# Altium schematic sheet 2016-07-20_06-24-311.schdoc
size 201 x 114 mm; SheetNumber: 1; SheetTotal: 1
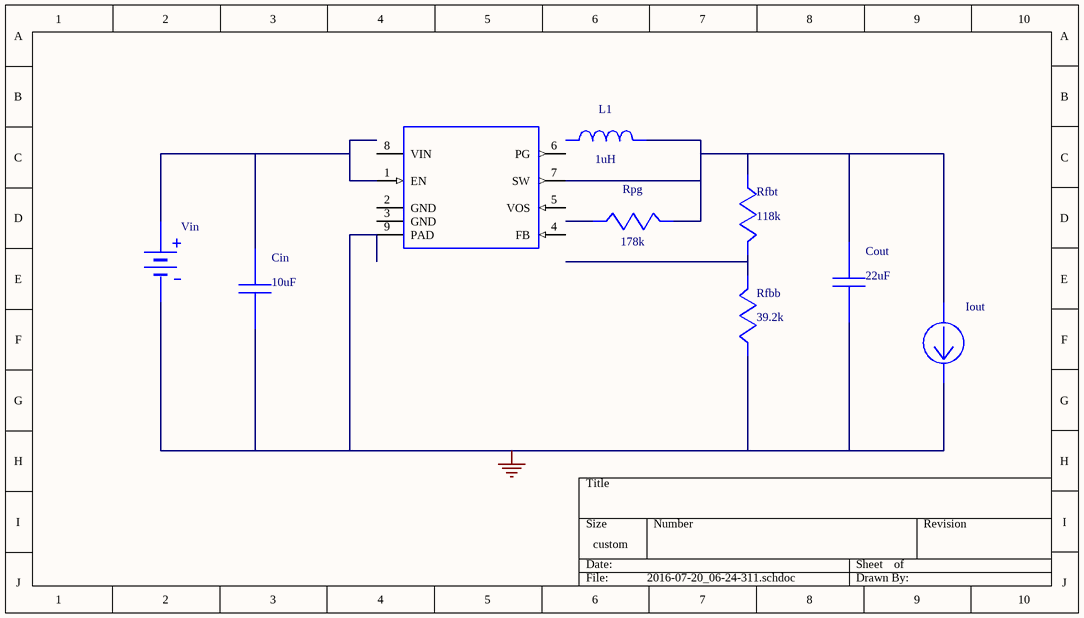
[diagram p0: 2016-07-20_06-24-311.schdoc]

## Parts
Cin  value 10uF  (hidden comment: JMK212BJ106KD-T)
Cout  value 22uF  (hidden comment: JMK212BJ226KG-T)
Iout  WB_CURRENT_LOAD  (value not drawn)
L1  value 1uH  (hidden comment: PFL3215-102MEB)
Rfbb  value 39.2k  (hidden comment: CRCW040239K2FKED)
Rfbt  value 118k  (hidden comment: CRCW0402118KFKED)
Rpg  value 178k  (hidden comment: CRCW0402178KFKED)
U1  TLV62084DSGR  (value not drawn)
Vin  WB_BATTERY  (value not drawn)

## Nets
0: Cin.2 Cout.2 Iout.2(-) Rfbb.2 U1.9(PAD) Vin.2(-)
NetCin_1: Cin.1 U1.1(EN) Vin.1(+)
NetCout_1: Cout.1 Iout.1(+) L1.2 Rfbt.2 Rpg.1 U1.7(SW)
NetRfbb_1: Rfbb.1 Rfbt.1

Not connected (* = marked no-connect by the designer): L1 1; Rpg 2; U1 2(GND) 3(GND) 4(FB) 5(VOS) 6(PG) 8(VIN)

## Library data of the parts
Cin = JMK212BJ106KD-T: Manufacturer Name: Taiyo Yuden
Cout = JMK212BJ226KG-T: Manufacturer Name: Taiyo Yuden
L1 = PFL3215-102MEB: Unknown; Manufacturer Name: Coilcraft
Rfbb = CRCW040239K2FKED: Manufacturer Name: Vishay-Dale
Rfbt = CRCW0402118KFKED: Manufacturer Name: Vishay-Dale
Rpg = CRCW0402178KFKED: Manufacturer Name: Vishay-Dale
U1 = TLV62084DSGR: Manufacturer Name: Texas Instruments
